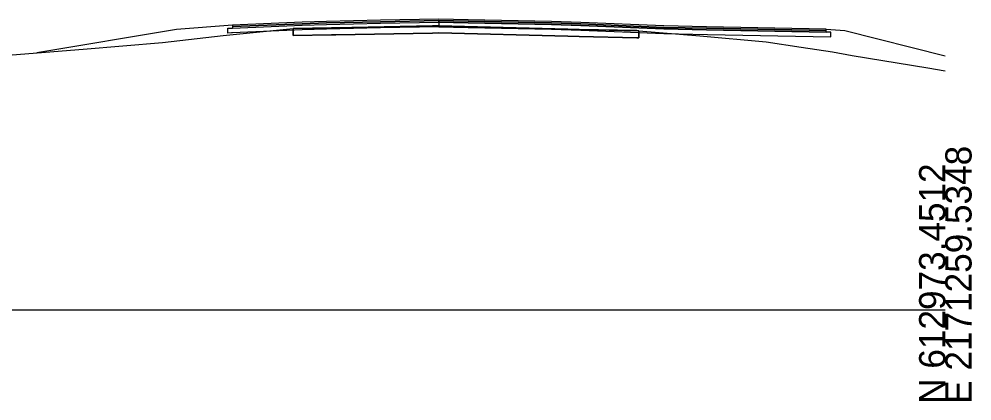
# Model space of a CAD drawing. Extents: x -26 to 1303, y -3010 to 12038.
# Drawn here: x 201.2 to 302.8, y 5490.3 to 5531 of the extents above; entities that cross this region are included whole.
import ezdxf

# ---------------------------------------------------------------- set-up
doc = ezdxf.new("R2010")
doc.units = 0
for name, color, linetype in [('RD_GPK_XS_Cell', 7, 'Continuous'), ('RD_XS_Base', 7, 'Continuous'), ('RD_XS_ExGround', 7, 'Continuous'), ('RD_XS_ExPaveRet', 7, 'Continuous'), ('RD_XS_Greenside', 7, 'Continuous'), ('RD_XS_Pave', 7, 'Continuous'), ('RD_XS_PaveOvlay_CP', 7, 'Continuous'), ('RD_XS_TieSlope', 7, 'Continuous')]:
    doc.layers.add(name, color=color, linetype=linetype)

msp = doc.modelspace()

# ---------------------------------------------------------------- linework, layer by layer
at = {"layer": 'RD_GPK_XS_Cell'}
msp.add_line((150, 5500), (300, 5500), dxfattribs=at)
at = {"layer": 'RD_XS_Base'}
for p, q in [((223.98, 5530.02), (231.4, 5530.32)), ((231.4, 5530.32), (233.98, 5530.42)), ((233.98, 5530.42), (239.75, 5530.54)), ((239.75, 5530.54), (245.98, 5530.66)), ((245.98, 5530.16), (239.75, 5530.04)), ((245.98, 5530.78), (245.98, 5530.82)), ((245.98, 5530.82), (245.98, 5530.65)), ((245.98, 5530.66), (245.98, 5530.78)), ((245.98, 5530.66), (245.98, 5530.66)), ((249.1, 5530.6), (245.98, 5530.66)), ((245.98, 5530.66), (245.98, 5530.66)), ((245.98, 5530.66), (245.98, 5530.53)), ((245.98, 5530.65), (245.98, 5530.16)), ((245.98, 5530.53), (245.98, 5530.16)), ((245.98, 5530.16), (249.1, 5530.1)), ((257.98, 5530.42), (249.1, 5530.6)), ((261.11, 5530.3), (257.98, 5530.42)), ((269.98, 5529.94), (261.11, 5530.3)), ((223.48, 5530), (223.85, 5530.02)), ((223.48, 5529.88), (223.48, 5530)), ((223.48, 5529.5), (223.48, 5529.88)), ((223.85, 5529.52), (223.48, 5529.5)), ((223.85, 5530.02), (223.98, 5530.02)), ((223.98, 5529.52), (223.85, 5529.52)), ((231.4, 5529.82), (223.98, 5529.52)), ((233.98, 5529.92), (231.4, 5529.82)), ((239.75, 5530.04), (233.98, 5529.92)), ((249.1, 5530.1), (257.98, 5529.92)), ((257.98, 5529.92), (261.11, 5529.8)), ((261.11, 5529.8), (269.98, 5529.44)), ((274.51, 5529.85), (269.98, 5529.94)), ((269.98, 5529.44), (274.64, 5529.35)), ((287.28, 5529.6), (274.51, 5529.85)), ((274.64, 5529.35), (287.78, 5529.09)), ((287.41, 5529.6), (287.28, 5529.6)), ((287.78, 5529.59), (287.41, 5529.6)), ((287.78, 5529.46), (287.78, 5529.59)), ((287.78, 5529.09), (287.78, 5529.46))]:
    msp.add_line(p, q, dxfattribs=at)
at = {"layer": 'RD_XS_ExGround'}
msp.add_lwpolyline([(199.58, 5527.11), (208.04, 5527.77), (216.51, 5528.5), (222.98, 5529.22), (230.43, 5529.99), (234.98, 5530.06), (245.97, 5530.26), (260.93, 5529.89), (267.32, 5529.74), (273.8, 5529.2), (280.9, 5528.55), (284.64, 5527.98), (287.97, 5527.5), (290.06, 5527.12), (298.13, 5525.78), (300, 5525.47)], dxfattribs=at)
at = {"layer": 'RD_XS_ExPaveRet'}
for p, q in [((245.3, 5530.25), (234.98, 5530.06)), ((245.97, 5530.26), (245.3, 5530.25)), ((259.72, 5529.92), (245.97, 5530.26)), ((267.32, 5529.74), (267.1, 5529.75))]:
    msp.add_line(p, q, dxfattribs=at)
for points in [[(267.1, 5529.75), (267.32, 5529.74), (267.32, 5529.04), (267.32, 5528.99), (267.1, 5529), (260.93, 5529.14), (259.72, 5529.17), (245.97, 5529.51), (245.3, 5529.5), (234.98, 5529.31), (234.51, 5529.31), (230.43, 5529.24), (230.43, 5529.29), (230.43, 5529.99), (234.51, 5530.06), (234.98, 5530.06), (245.3, 5530.25), (245.97, 5530.26), (259.72, 5529.92), (260.93, 5529.89), (267.1, 5529.75)], [(234.98, 5530.06), (234.51, 5530.06), (230.43, 5529.99)], [(230.43, 5529.99), (230.43, 5529.29), (230.43, 5529.24), (234.51, 5529.31), (234.98, 5529.31), (245.3, 5529.5), (245.97, 5529.51), (259.72, 5529.17), (260.93, 5529.14), (267.1, 5529), (267.32, 5528.99), (267.32, 5529.04), (267.32, 5529.74)], [(267.1, 5529.75), (260.93, 5529.89), (259.72, 5529.92)]]:
    msp.add_lwpolyline(points, dxfattribs=at)
at = {"layer": 'RD_XS_Greenside'}
for p, q in [((217.98, 5529.86), (203.1, 5527.38)), ((289.28, 5529.76), (300, 5527.08))]:
    msp.add_line(p, q, dxfattribs=at)
at = {"layer": 'RD_XS_Pave'}
for p, q in [((231.4, 5530.64), (223.98, 5530.34)), ((231.4, 5530.48), (223.98, 5530.18)), ((223.98, 5530.18), (231.4, 5530.48)), ((223.98, 5530.34), (223.98, 5530.3)), ((223.98, 5530.02), (231.4, 5530.32)), ((223.98, 5530.3), (223.98, 5530.18)), ((223.98, 5530.18), (223.98, 5530.14)), ((223.98, 5530.14), (223.98, 5530.02)), ((233.98, 5530.74), (231.4, 5530.64)), ((233.98, 5530.58), (231.4, 5530.48)), ((231.4, 5530.48), (233.98, 5530.58)), ((231.4, 5530.32), (233.98, 5530.42)), ((239.75, 5530.86), (233.98, 5530.74)), ((239.75, 5530.7), (233.98, 5530.58)), ((233.98, 5530.58), (239.75, 5530.7)), ((233.98, 5530.42), (239.75, 5530.54)), ((245.98, 5530.98), (239.75, 5530.86)), ((245.98, 5530.82), (239.75, 5530.7)), ((239.75, 5530.7), (245.98, 5530.82)), ((239.75, 5530.54), (245.98, 5530.66)), ((249.1, 5530.92), (245.98, 5530.98)), ((245.98, 5530.78), (245.98, 5530.82)), ((245.98, 5530.82), (249.1, 5530.76)), ((249.1, 5530.76), (245.98, 5530.82)), ((245.98, 5530.82), (245.98, 5530.82)), ((245.98, 5530.82), (245.98, 5530.82)), ((245.98, 5530.82), (245.98, 5530.78)), ((245.98, 5530.66), (245.98, 5530.78)), ((245.98, 5530.78), (245.98, 5530.66)), ((245.98, 5530.66), (245.98, 5530.66)), ((245.98, 5530.66), (245.98, 5530.66)), ((245.98, 5530.66), (249.1, 5530.6)), ((257.98, 5530.74), (249.1, 5530.92)), ((249.1, 5530.76), (257.98, 5530.58)), ((257.98, 5530.58), (249.1, 5530.76)), ((249.1, 5530.6), (257.98, 5530.42)), ((261.11, 5530.62), (257.98, 5530.74)), ((257.98, 5530.58), (261.11, 5530.46)), ((261.11, 5530.46), (257.98, 5530.58)), ((257.98, 5530.42), (261.11, 5530.3)), ((269.98, 5530.26), (261.11, 5530.62)), ((261.11, 5530.46), (269.98, 5530.1)), ((269.98, 5530.1), (261.11, 5530.46)), ((261.11, 5530.3), (269.98, 5529.94)), ((274.51, 5530.17), (269.98, 5530.26)), ((287.28, 5529.92), (274.51, 5530.17)), ((269.98, 5530.1), (274.51, 5530.01)), ((274.51, 5530.01), (269.98, 5530.1)), ((269.98, 5529.94), (274.51, 5529.85)), ((274.51, 5530.01), (287.28, 5529.76)), ((287.28, 5529.76), (274.51, 5530.01)), ((274.51, 5529.85), (287.28, 5529.6)), ((287.28, 5529.88), (287.28, 5529.92)), ((287.28, 5529.76), (287.28, 5529.88)), ((287.28, 5529.72), (287.28, 5529.76)), ((287.28, 5529.6), (287.28, 5529.72))]:
    msp.add_line(p, q, dxfattribs=at)
at = {"layer": 'RD_XS_PaveOvlay_CP'}
for p, q in [((231.4, 5530.64), (223.98, 5530.34)), ((233.98, 5530.74), (231.4, 5530.64)), ((239.75, 5530.86), (233.98, 5530.74)), ((245.98, 5530.98), (239.75, 5530.86)), ((249.1, 5530.92), (245.98, 5530.98)), ((257.98, 5530.74), (249.1, 5530.92)), ((261.11, 5530.62), (257.98, 5530.74)), ((269.98, 5530.26), (261.11, 5530.62)), ((274.51, 5530.17), (269.98, 5530.26)), ((287.28, 5529.92), (274.51, 5530.17))]:
    msp.add_line(p, q, dxfattribs=at)
at = {"layer": 'RD_XS_TieSlope'}
for p, q in [((223.98, 5530.34), (217.98, 5529.86)), ((287.28, 5529.92), (289.28, 5529.76))]:
    msp.add_line(p, q, dxfattribs=at)

# ---------------------------------------------------------------- texts
at = {"layer": 'RD_GPK_XS_Cell'}
for s, p in [('E 2171259.5348', (302.8, 5490)), ('N 612973.4512', (300, 5490))]:
    msp.add_text(s, height=2.8, rotation=90, dxfattribs=at).set_placement(p)

doc.saveas('drawing.dxf')
